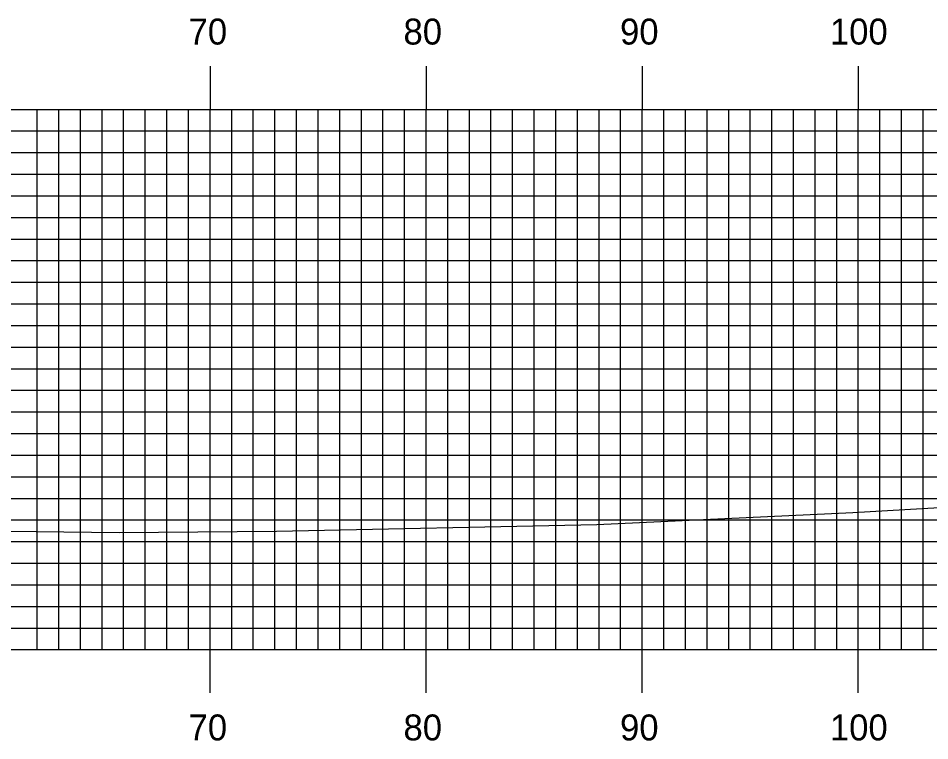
# Model space of a CAD drawing. Extents: x 1819244 to 1819587, y 442591 to 442811.
# Drawn here: x 1819470.79 to 1819512.97, y 442649.45 to 442682.88 of the extents above; entities that cross this region are included whole.
import ezdxf

# ---------------------------------------------------------------- set-up
doc = ezdxf.new("R2010")
doc.units = 0
for name, color, linetype in [('H_V ANNOTATION', 7, 'Continuous'), ('MAJOR', 7, 'Continuous'), ('MINOR', 7, 'Continuous'), ('S_Roadway_Centerline', 7, 'Continuous')]:
    doc.layers.add(name, color=color, linetype=linetype)

msp = doc.modelspace()

# ---------------------------------------------------------------- linework, layer by layer
at = {"layer": 'MAJOR'}
for p, q in [((1819479.665, 442680.669), (1819479.665, 442678.665)), ((1819489.665, 442680.669), (1819489.665, 442678.665)), ((1819499.665, 442680.669), (1819499.665, 442678.665)), ((1819509.665, 442680.669), (1819509.665, 442678.665)), ((1819269.665, 442678.665), (1819549.665, 442678.665)), ((1819269.665, 442678.665), (1819549.665, 442678.665)), ((1819479.665, 442653.665), (1819479.665, 442678.665)), ((1819489.665, 442653.665), (1819489.665, 442678.665)), ((1819499.665, 442653.665), (1819499.665, 442678.665)), ((1819509.665, 442653.665), (1819509.665, 442678.665)), ((1819269.665, 442673.665), (1819549.665, 442673.665)), ((1819269.665, 442668.665), (1819549.665, 442668.665)), ((1819269.665, 442663.665), (1819549.665, 442663.665)), ((1819269.665, 442658.665), (1819549.665, 442658.665)), ((1819269.665, 442653.665), (1819549.665, 442653.665)), ((1819269.665, 442653.665), (1819549.665, 442653.665)), ((1819479.665, 442651.661), (1819479.665, 442653.665)), ((1819489.665, 442651.661), (1819489.665, 442653.665)), ((1819499.665, 442651.661), (1819499.665, 442653.665)), ((1819509.665, 442651.661), (1819509.665, 442653.665))]:
    msp.add_line(p, q, dxfattribs=at)
at = {"layer": 'MINOR'}
for p, q in [((1819471.665, 442653.665), (1819471.665, 442678.665)), ((1819472.665, 442653.665), (1819472.665, 442678.665)), ((1819473.665, 442653.665), (1819473.665, 442678.665)), ((1819474.665, 442653.665), (1819474.665, 442678.665)), ((1819475.665, 442653.665), (1819475.665, 442678.665)), ((1819476.665, 442653.665), (1819476.665, 442678.665)), ((1819477.665, 442653.665), (1819477.665, 442678.665)), ((1819478.665, 442653.665), (1819478.665, 442678.665)), ((1819480.665, 442653.665), (1819480.665, 442678.665)), ((1819481.665, 442653.665), (1819481.665, 442678.665)), ((1819482.665, 442653.665), (1819482.665, 442678.665)), ((1819483.665, 442653.665), (1819483.665, 442678.665)), ((1819484.665, 442653.665), (1819484.665, 442678.665)), ((1819485.665, 442653.665), (1819485.665, 442678.665)), ((1819486.665, 442653.665), (1819486.665, 442678.665)), ((1819487.665, 442653.665), (1819487.665, 442678.665)), ((1819488.665, 442653.665), (1819488.665, 442678.665)), ((1819490.665, 442653.665), (1819490.665, 442678.665)), ((1819491.665, 442653.665), (1819491.665, 442678.665)), ((1819492.665, 442653.665), (1819492.665, 442678.665)), ((1819493.665, 442653.665), (1819493.665, 442678.665)), ((1819494.665, 442653.665), (1819494.665, 442678.665)), ((1819495.665, 442653.665), (1819495.665, 442678.665)), ((1819496.665, 442653.665), (1819496.665, 442678.665)), ((1819497.665, 442653.665), (1819497.665, 442678.665)), ((1819498.665, 442653.665), (1819498.665, 442678.665)), ((1819500.665, 442653.665), (1819500.665, 442678.665)), ((1819501.665, 442653.665), (1819501.665, 442678.665)), ((1819502.665, 442653.665), (1819502.665, 442678.665)), ((1819503.665, 442653.665), (1819503.665, 442678.665)), ((1819504.665, 442653.665), (1819504.665, 442678.665)), ((1819505.665, 442653.665), (1819505.665, 442678.665)), ((1819506.665, 442653.665), (1819506.665, 442678.665)), ((1819507.665, 442653.665), (1819507.665, 442678.665)), ((1819508.665, 442653.665), (1819508.665, 442678.665)), ((1819510.665, 442653.665), (1819510.665, 442678.665)), ((1819511.665, 442653.665), (1819511.665, 442678.665)), ((1819512.665, 442653.665), (1819512.665, 442678.665)), ((1819269.665, 442677.665), (1819549.665, 442677.665)), ((1819269.665, 442676.665), (1819549.665, 442676.665)), ((1819269.665, 442675.665), (1819549.665, 442675.665)), ((1819269.665, 442674.665), (1819549.665, 442674.665)), ((1819269.665, 442672.665), (1819549.665, 442672.665)), ((1819269.665, 442671.665), (1819549.665, 442671.665)), ((1819269.665, 442670.665), (1819549.665, 442670.665)), ((1819269.665, 442669.665), (1819549.665, 442669.665)), ((1819269.665, 442667.665), (1819549.665, 442667.665)), ((1819269.665, 442666.665), (1819549.665, 442666.665)), ((1819269.665, 442665.665), (1819549.665, 442665.665)), ((1819269.665, 442664.665), (1819549.665, 442664.665)), ((1819269.665, 442662.665), (1819549.665, 442662.665)), ((1819269.665, 442661.665), (1819549.665, 442661.665)), ((1819269.665, 442660.665), (1819549.665, 442660.665)), ((1819269.665, 442659.665), (1819549.665, 442659.665)), ((1819269.665, 442657.665), (1819549.665, 442657.665)), ((1819269.665, 442656.665), (1819549.665, 442656.665)), ((1819269.665, 442655.665), (1819549.665, 442655.665)), ((1819269.665, 442654.665), (1819549.665, 442654.665))]:
    msp.add_line(p, q, dxfattribs=at)
at = {"layer": 'S_Roadway_Centerline'}
msp.add_lwpolyline([(1819453.663, 442659.344), (1819475.455, 442659.085), (1819482.736, 442659.152), (1819497.564, 442659.463), (1819509.416, 442660.014), (1819517.174, 442660.466), (1819524.87, 442660.759), (1819537.148, 442661.896), (1819542.486, 442662.603), (1819549.665, 442663.134)], dxfattribs=at)

# ---------------------------------------------------------------- texts
at = {"layer": 'H_V ANNOTATION'}
for s, p in [('70', (1819478.669, 442681.665)), ('80', (1819488.615, 442681.665)), ('90', (1819498.637, 442681.665)), ('100', (1819508.348, 442681.665)), ('70', (1819478.669, 442649.465)), ('80', (1819488.615, 442649.465)), ('90', (1819498.637, 442649.465)), ('100', (1819508.348, 442649.465))]:
    msp.add_text(s, height=1.2, dxfattribs=at).set_placement(p)

doc.saveas('drawing.dxf')
